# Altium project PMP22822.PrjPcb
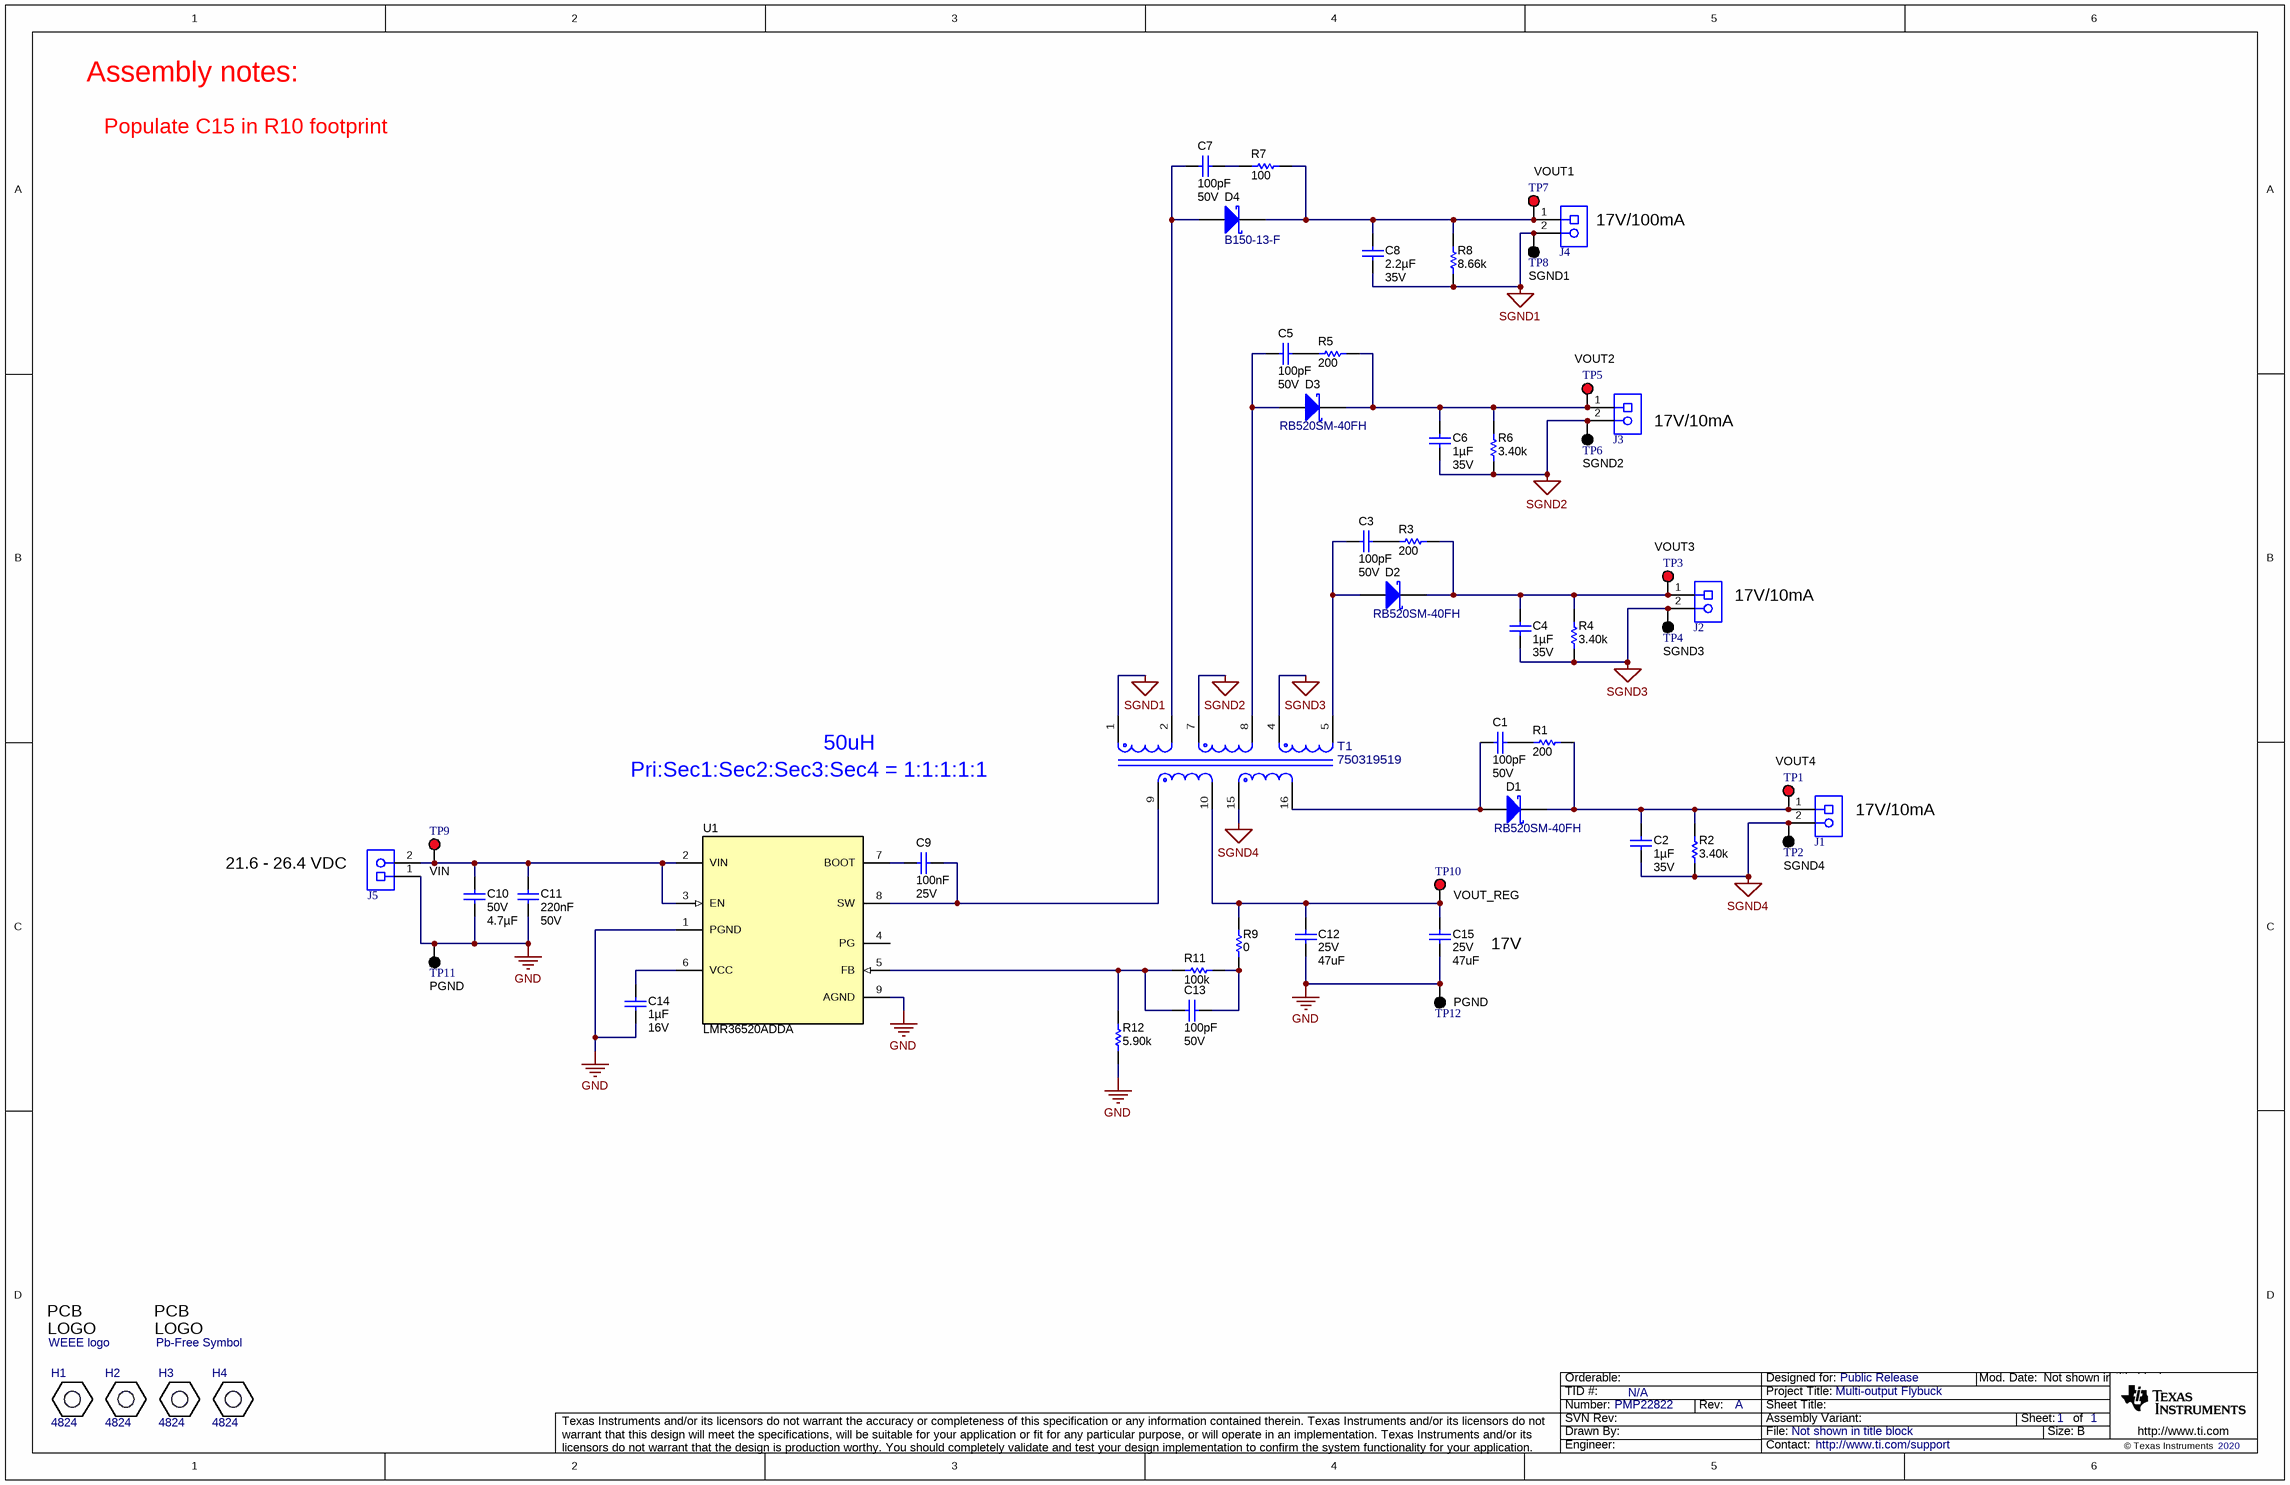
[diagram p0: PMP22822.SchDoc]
TID: N/A; TechSupport: http://www.ti.com/support; SCH_Rev: A; PRJ_Title: Multi-output Flybuck; PRJ_Number: PMP22822; PRJ_Customer: Public Release; PCB_Rev: A; Engineer: B Genereaux; CopyrightYear: 2020
1 sheet, 55 parts. Net scope: global (net labels, ports and power ports of the same name join across sheets).
Board file: PMP22822.PcbDoc

## Sheet PMP22822.SchDoc
size 431 x 279 mm; Date: Not shown in title block; ApprovedBy: Not shown in title block; CheckedBy: Not shown in title block; Author: Not shown in title block; CompanyName: Not shown in title block; Engineer: Not shown in title block; Organization: Not shown in title block; Address1: Not shown in title block; Address2: Not shown in title block; Address3: Not shown in title block; Address4: Not shown in title block; DocumentNumber: 1; Revision: Use project parameter SCH_Rev; SheetNumber: 1; SheetTotal: 1; PageSetup: Record=PageOptions¦CenterHorizontal=True¦CenterVertical=True¦PrintScale=1.00¦XCorrection=1.00¦YCorrection=1.00¦PrintKind=0¦BorderSize=5000000¦LeftOffset=0¦BottomOffset=0¦Orientation=2¦PaperLength=1000¦PaperWidth=1000¦Scale=100¦PaperSource=15¦PrintQuality=600¦MediaType=1¦DitherType=10¦PaperKind=Letter¦PrintScaleMode=1

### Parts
C1  Cap_F: 100pF  VDC_V: 50V  [0603]  (hidden comment: CL10B101KB8NNNC)
C2  Cap_F: 1µF  VDC_V: 35V  [0603]  (hidden comment: C1608X7R1V105K080AC)
C3  Cap_F: 100pF  VDC_V: 50V  [0603]  (hidden comment: CL10B101KB8NNNC)
C4  Cap_F: 1µF  VDC_V: 35V  [0603]  (hidden comment: C1608X7R1V105K080AC)
C5  Cap_F: 100pF  VDC_V: 50V  [0603]  (hidden comment: CL10B101KB8NNNC)
C6  Cap_F: 1µF  VDC_V: 35V  [0603]  (hidden comment: C1608X7R1V105K080AC)
C7  Cap_F: 100pF  VDC_V: 50V  [0603]  (hidden comment: CL10B101KB8NNNC)
C8  Cap_F: 2.2µF  VDC_V: 35V  [0805_HV]  (hidden comment: C2012X7R1V225K085AC)
C9  Cap_F: 100nF  VDC_V: 25V  [0603]  (hidden comment: C0603X104K3RACTU)
C10  VDC_V: 50V  ValueDisplayed: 4.7µF  [1206_190M]  (hidden comment: C3216X7R1H475K160AE)
C11  Cap_F: 220nF  VDC_V: 50V  [0603]  (hidden comment: GRM188R71H224KAC4D)
C12  VDC_V: 25V  ValueDisplayed: 47uF  [1206_190]  (hidden comment: C3216X5R1E476M160AC)
C13  Cap_F: 100pF  VDC_V: 50V  [0603]  (hidden comment: CL10B101KB8NNNC)
C14  Cap_F: 1µF  VDC_V: 16V  [0805_HV]  (hidden comment: GRM21BR71C105KA01L)
C15  VDC_V: 25V  ValueDisplayed: 47uF  [1206_190]  (hidden comment: C3216X5R1E476M160AC)
D1  RB520SM-40FH  [SOD-523]
D2  RB520SM-40FH  [SOD-523]
D3  RB520SM-40FH  [SOD-523]
D4  B150-13-F  [SMA]
H1  4824  [KEYSTONE_4824]
H2  4824  [KEYSTONE_4824]
H3  4824  [KEYSTONE_4824]
H4  4824  [KEYSTONE_4824]
J1  ED555/2DS  [TERM_BLK_ED555-2DS]  (value not drawn)
J2  ED555/2DS  [TERM_BLK_ED555-2DS]  (value not drawn)
J3  ED555/2DS  [TERM_BLK_ED555-2DS]  (value not drawn)
J4  ED555/2DS  [TERM_BLK_ED555-2DS]  (value not drawn)
J5  ED555/2DS  [TERM_BLK_ED555-2DS]  (value not drawn)
Logo1  WEEE logo  [WEEE_Minimum]  (no BOM)
Logo2  Pb-Free Symbol  [Pb-Free_Overlay_Medium]  (no BOM)
R1  ValueDisplayed: 200  [0603]  (hidden comment: RC0603FR-07200RL)
R2  ValueDisplayed: 3.40k  [0603]  (hidden comment: M55342K12B3E40T)
R3  ValueDisplayed: 200  [0603]  (hidden comment: RC0603FR-07200RL)
R4  ValueDisplayed: 3.40k  [0603]  (hidden comment: M55342K12B3E40T)
R5  ValueDisplayed: 200  [0603]  (hidden comment: RC0603FR-07200RL)
R6  ValueDisplayed: 3.40k  [0603]  (hidden comment: M55342K12B3E40T)
R7  ValueDisplayed: 100  [0603]  (hidden comment: RC0603FR-07100RL)
R8  ValueDisplayed: 8.66k  [0805_HV]  (hidden comment: ERJ-6ENF8661V)
R9  ValueDisplayed: 0  [0603]  (hidden comment: RMCF0603ZT0R00)
R11  ValueDisplayed: 100k  [0603]  (hidden comment: RC0603FR-07100KL)
R12  ValueDisplayed: 5.90k  [0603]  (hidden comment: RC0603FR-075K9L)
T1  750319519  [FP-750319519_SMT_XFRMR_17MM46_16MM51-MFG]
TP1  VOUT4  [Keystone5000]
TP2  SGND4  [Keystone5001]
TP3  VOUT3  [Keystone5000]
TP4  SGND3  [Keystone5001]
TP5  VOUT2  [Keystone5000]
TP6  SGND2  [Keystone5001]
TP7  VOUT1  [Keystone5000]
TP8  SGND1  [Keystone5001]
TP9  VIN  [Keystone5000]
TP10  VOUT_REG  [Keystone5000]
TP11  PGND  [Keystone5001]
TP12  PGND  [Keystone5001]
U1  LMR36520ADDA  [DDA0008J]

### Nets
GND: C10.2 C11.2 C12.2 C14.2 C15.2 J5.1 R12.1 TP11.1 TP12.1 U1.1(PGND) U1.9(AGND)
SGND1: C8.2 J4.2 R8.1 T1.1 TP8.1
SGND2: C6.2 J3.2 R6.1 T1.7 TP6.1
SGND3: C4.2 J2.2 R4.1 T1.4 TP4.1
SGND4: C2.2 J1.2 R2.1 T1.15 TP2.1
NetC1_1: C1.1 R1.1
NetC1_2: C1.2 D1.2(A) T1.16
NetC2_1: C2.1 D1.1(K) J1.1 R1.2 R2.2 TP1.1
NetC3_1: C3.1 R3.1
NetC3_2: C3.2 D2.2(A) T1.5
NetC4_1: C4.1 D2.1(K) J2.1 R3.2 R4.2 TP3.1
NetC5_1: C5.1 R5.1
NetC5_2: C5.2 D3.2(A) T1.8
NetC6_1: C6.1 D3.1(K) J3.1 R5.2 R6.2 TP5.1
NetC7_1: C7.1 R7.1
NetC7_2: C7.2 D4.2(A) T1.2
NetC8_1: C8.1 D4.1(K) J4.1 R7.2 R8.2 TP7.1
NetC9_1: C9.1 T1.9 U1.8(SW)
NetC9_2: C9.2 U1.7(BOOT)
NetC10_1: C10.1 C11.1 J5.2 TP9.1 U1.2(VIN) U1.3(EN)
NetC12_1: C12.1 C15.1 R9.2 T1.10 TP10.1
NetC13_1: C13.1 R9.1 R11.1
NetC13_2: C13.2 R11.2 R12.2 U1.5(FB)
NetC14_1: C14.1 U1.6(VCC)

Not connected (* = marked no-connect by the designer): U1 4(PG)

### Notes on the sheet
- Assembly notes:
- Populate C15 in R10 footprint
- (near J4) 17V/100mA
- 17V/10mA
- Pri:Sec1:Sec2:Sec3:Sec4 = 1:1:1:1:1
- 50uH
- (near J5) 21.6 - 26.4 VDC
- 17V

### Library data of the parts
C1 C3 C5 C7 C13 = CMP-0083857-1: CAP, CERM, 100 pF, 50 V,+/- 10%, X7R, 0603; Manufacturer: Samsung Electro-Mechanics; TaMin_C: -55°C; Polarized: N; SizeAreaWB_mm2: 4.68; U/M: EA; Value: 100pF; TaMax_C: 125°C; SizeZ_mm: 1; SizeX_mm: 1.6; SizeY_mm: 0.8; SizeArea_mm2: 1.28; AEC Category: Q200
C2 C4 C6 = CMP-0007052-4: CAP, CERM, 1 uF, 35 V, +/- 10%, X7R, 0603; Manufacturer: TDK; TaMin_C: -55°C; Polarized: N; SizeAreaWB_mm2: 4.68; Value1: Unknown; U/M: EA; Value: 1uF; TaMax_C: 125°C; SizeZ_mm: 1; SizeX_mm: 1.6; SizeY_mm: 0.8; SizeArea_mm2: 1.28; AEC Category: Q200
C8 = CMP-0007883-2: CAP, CERM, 2.2 uF, 35 V, +/- 10%, X7R, 0805; Manufacturer: TDK; TaMin_C: -55°C; Polarized: N; SizeAreaWB_mm2: 6.75; Value1: Unknown; U/M: EA; Value: 2.2uF; TaMax_C: 125°C; SizeZ_mm: 1.45; SizeX_mm: 2; SizeY_mm: 1.25; Cap_Case: 0805; SizeArea_mm2: 2.5; AEC Category: Q200
C9 = CMP-0006979-5: CAP, CERM, 0.1 uF, 25 V, +/- 10%, X7R, 0603; Manufacturer: Kemet; TaMin_C: -55°C; Polarized: N; SizeAreaWB_mm2: 4.68; Value1: Unknown; U/M: EA; Value: 0.1uF; TaMax_C: 125°C; SizeZ_mm: 1; SizeX_mm: 1.6; SizeY_mm: 0.8; SizeArea_mm2: 1.28; AEC Category: Q200
C10 = CMP-0082522-1: CAP, CERM, 4.7 µF, 50 V,+/- 10%, X7R, 1206; Manufacturer: TDK; SizeAreaWB_mm2: 10.92; SizeArea_mm2: 5.12; AEC Qualified: N; AEC Category: Q200; Value: 4.7uF; TaMax_C: 125°C; SizeZ_mm: 1.9; TaMin_C: -55°C; SizeY_mm: 1.6; U/M: EA; SizeX_mm: 3.2; Cap_Case: 1206
C11 = CMP-0007445-4: CAP, CERM, 0.22 uF, 50 V, +/- 10%, X7R, 0603; Manufacturer: MuRata; TaMin_C: -55°C; Polarized: N; SizeAreaWB_mm2: 4.68; Value1: Unknown; U/M: EA; Value: 0.22uF; TaMax_C: 125°C; SizeZ_mm: 1; SizeX_mm: 1.6; SizeY_mm: 0.8; SizeArea_mm2: 1.28; AEC Category: Q200
C12 C15 = CMP-0008656-2: CAP, CERM, 47 uF, 25 V, +/- 20%, X5R, 1206_190; Manufacturer: TDK; TaMin_C: -55°C; Polarized: N; SizeAreaWB_mm2: 10.92; Value1: Unknown; U/M: EA; Value: 47uF; TaMax_C: 85°C; SizeZ_mm: 1.9; SizeX_mm: 3.2; SizeY_mm: 1.6; Cap_Case: 1206; SizeArea_mm2: 5.12; Cap_F: 47µF; AEC Category: Q200
C14 = CMP-0008323-2: CAP, CERM, 1 uF, 16 V, +/- 10%, X7R, 0805; Manufacturer: MuRata; TaMin_C: -55°C; ESR_ohm: 3m; Polarized: N; SizeAreaWB_mm2: 6.75; Value1: 0.003 ohm; U/M: EA; Value: 1uF; TaMax_C: 125°C; SizeZ_mm: 1.45; SizeX_mm: 2; SizeY_mm: 1.25; Cap_Case: 0805; SizeArea_mm2: 2.5; AEC Category: Q200
D1-D3 = CMP-0077062-3: Diode, Schottky, 45 V, 0.2 A, AEC-Q101, SOD-523; Manufacturer: Rohm; TJmax_C: 150°C; SizeAreaWB_mm2: 5.13; Vr_V: 45V; SizeZ_mm: 0.65; SizeArea_mm2: 1.53; SizeY_mm: 0.9; Vf_V: 550mV; Value2: 0.55V; SizeX_mm: 1.7; Value: 45V; Green_REACh: Incomplete; AEC Category: Q101; Value1: 0.2A; Green_Lifecycle: Not Set; Io_A: 200mA; AEC Qualified: Y
D4 = CMP-0028387-2: Diode, Schottky, 50 V, 1 A, SMA; Manufacturer: Diodes Inc.; Value1: 1A; SizeAreaWB_mm2: 37.3428; TJmax_C: 150°C; RJC_CperW: 20; SizeArea_mm2: 16.3228; Vf_V: 700mV; Value2: 0.7V; AEC Category: Q101; SizeZ_mm: 2.87; Vr_V: 50V; SizeY_mm: 2.92; Green_REACh: Passed; Value: 50V; SizeX_mm: 5.59; Green_Lifecycle: Active
H1-H4 = CMP-0003690-1: Manufacturer: Keystone; CompType: Standoff
J1-J5 = CMP-0074913-1: Terminal Block, 3.5mm Pitch, 2x1, TH; Manufacturer: On-Shore Technology; Cert_VDE: Y; CNHeader: False; Current_A: 6A; Green_Lifecycle: Active; Shrouded: N; Gender: Female; Green_REACh: Passed; Voltage_V: 150V; Row_Count: 1; Pitch_mm: 3.5; ContactFinish: Brass; CT: True
Logo1 = CMP-0074769-1
Logo2 = CMP-0074839-1: SymbolCreator: a0412235
R1 R3 R5 = CMP-0022902-5: RES, 200, 1%, 0.1 W, 0603; Manufacturer: Yageo; Power_W: 100mW; TempCo: 100 ppm/C; Value_Code: 200R; Value: 200; EIA_Code: E96; SizeX_mm: 1.6; SizeY_mm: 0.8; SizeZ_mm: 1; Value2: 0.1W; SizeArea_mm2: 1.28; AEC Qualified: N; VDC_V: 75V; AEC Category: Q200; SizeAreaWB_mm2: 4.68
R2 R4 R6 = CMP-0080491-1: RES, 3.40 k, 1%, 0.1 W, 0603; Manufacturer: TT Electronics/IRC; Power_W: 100mW; TempCo: 100 ppm/C; SizeAreaWB_mm2: 4.68; Value_Code: 3k40; Value: 3.40k; EIA_Code: E96; Res_ohm: 3.4k; SizeX_mm: 1.6; SizeY_mm: 0.8; SizeZ_mm: 1; Value2: 0.1W; SizeArea_mm2: 1.28; AEC Qualified: N; AEC Category: Q200
R7 = CMP-0022736-4: RES, 100, 1%, 0.1 W, 0603; Manufacturer: Yageo; Power_W: 100mW; TempCo: 100 ppm/C; Value_Code: 100R; Value: 100; EIA_Code: E96; SizeX_mm: 1.6; SizeY_mm: 0.8; SizeZ_mm: 1; Value2: 0.1W; SizeArea_mm2: 1.28; AEC Qualified: N; VDC_V: 75V; AEC Category: Q200; SizeAreaWB_mm2: 4.68
R8 = CMP-0021803-3: RES, 8.66 k, 1%, 0.125 W, AEC-Q200 Grade 0, 0805; Manufacturer: Panasonic; Power_W: 125mW; TempCo: 100 ppm/C; Value_Code: 8k66; Value: 8.66k; EIA_Code: E96; SizeX_mm: 2; SizeY_mm: 1.25; SizeZ_mm: 1.45; Value2: 0.125W; SizeArea_mm2: 2.5; AEC Qualified: Y; AEC Category: Q200; AEC Grade: 0; SizeAreaWB_mm2: 6.75
R9 = CMP-0023343-3: RES, 0, 1%, 0.1 W, AEC-Q200 Grade 0, 0603; Manufacturer: Stackpole Electronics Inc; Power_W: 100mW; TempCo: ppm/C; U/M: EA; Value: 0; SizeX_mm: 1.6; SizeY_mm: 0.8; SizeZ_mm: 1; Value2: 0.1W; SizeArea_mm2: 1.28; AEC Qualified: Y; AEC Category: Q200
R11 = CMP-0022735-5: RES, 100 k, 1%, 0.1 W, 0603; Manufacturer: Yageo; Power_W: 100mW; TempCo: 100 ppm/C; Value: 100k; EIA_Code: E96; SizeX_mm: 1.6; SizeY_mm: 0.8; SizeZ_mm: 1; Value2: 0.1W; SizeArea_mm2: 1.28; AEC Qualified: N; VDC_V: 75V; AEC Category: Q200; SizeAreaWB_mm2: 4.68
R12 = CMP-0023205-5: RES, 5.90 k, 1%, 0.1 W, 0603; Manufacturer: Yageo; Power_W: 100mW; TempCo: 100 ppm/C; Value_Code: 5k90; Value: 5.90k; EIA_Code: E96; Res_ohm: 5.9k; SizeX_mm: 1.6; SizeY_mm: 0.8; SizeZ_mm: 1; Value2: 0.1W; SizeArea_mm2: 1.28; AEC Qualified: N; VDC_V: 75V; AEC Category: Q200; SizeAreaWB_mm2: 4.68
T1 = CMP-0091384-1: Tranformer, 0.15Ohm PRI, 0.35Ohm SEC, 42.5uH, 1:1:1:1:1, 4000VAC, 17.46x16.51x12.70mm SMT; Manufacturer: Wurth Electronics; Voltage_Isolation_Vrms: 4kV; Rsec1_ohm: 0.35; SizeZ_mm: 12.7mm; Frequency_Fixed: 400kHz; DCR_ohm: 0.15; Ind_H: 42.5µH; AEC Qualified: No
TP1 TP3 TP5 TP7 TP9 TP10 = CMP-0055137-1: Test Point, Miniature, Red, TH; Manufacturer: Keystone; CNHeader: FALSE; Green_Lifecycle: Active; Green_REACh: Passed; ContactFinish: Silver; CT: TRUE
TP2 TP4 TP6 TP8 TP11 TP12 = CMP-0055138-1: Test Point, Miniature, Black, TH; Manufacturer: Keystone; CNHeader: FALSE; Green_Lifecycle: Active; Green_REACh: Passed; ContactFinish: Silver; CT: TRUE
U1 = CMP-0860813-1: SIMPLE SWITCHER® 4.2-V to 65-V, 2-A Synchronous Step-down Converter, DDA0008J (HSOIC-8); Alternate Manufacturer: Texas Instruments; AEC Category: Q200; SizeAreaWB_mm2: 55.2; CompType: IC; SizeArea_mm2: 29.4; SizeX_mm: 6; SizeY_mm: 4.9; SizeZ_mm: 1.7; AEC Qualified: N

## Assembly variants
001: not fitted C1 C3 C5 C13 H1 H2 H3 H4 R1 R3 R5 R10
